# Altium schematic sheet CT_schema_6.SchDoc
size 287 x 160 mm
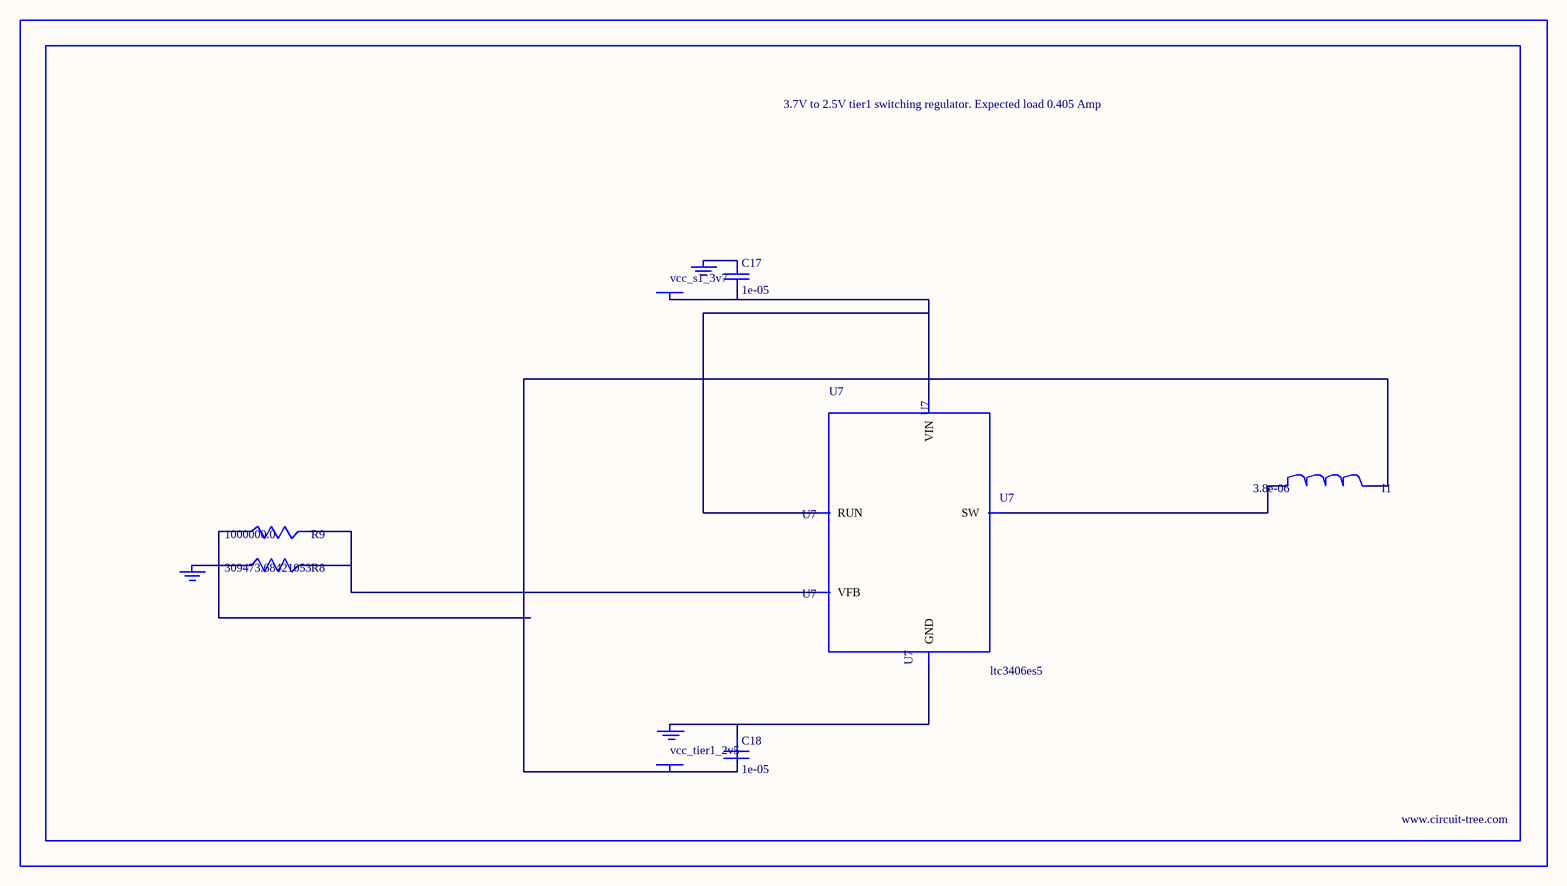
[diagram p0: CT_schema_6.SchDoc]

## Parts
BORDER5  (no value)
C17  1e-05  [C0805]
C18  1e-05  [C0805]
GND_INSTANCE_5_0  (no value)
GND_INSTANCE_5_1  (no value)
GND_INSTANCE_5_2  (no value)
I1  3.8e-06  [DR1040]
POWER_INSTANCE_5_0  vcc_tier1_2v5
POWER_INSTANCE_5_1  vcc_s1_3v7
R8  309473.68421053  [R0603]
R9  1000000.0  [R0603]
U7  ltc3406es5  [TSOT-23-5]

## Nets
NetC17_1: C17.1 GND_INSTANCE_5_1.0(GND)
NetC17_2: C17.2 POWER_INSTANCE_5_1.0(PWR) U7.1(RUN) U7.4(VIN)
NetC18_1: C18.1 GND_INSTANCE_5_0.0(GND) U7.2(GND)
NetC18_2: C18.2 I1.2 POWER_INSTANCE_5_0.0(PWR) R9.1
NetGND_INSTANCE_5_2_0: GND_INSTANCE_5_2.0(GND) R8.1
NetI1_1: I1.1 U7.3(SW)
NetR8_2: R8.2 R9.2 U7.5(VFB)

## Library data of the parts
BORDER5 = BORDER_PAGE5
C17 C18 = C0805C106K8RACTU
GND_INSTANCE_5_0-GND_INSTANCE_5_2 = GND
I1 = DR1040-3R8-R
POWER_INSTANCE_5_0 POWER_INSTANCE_5_1 = PWR
R8 = R8
R9 = RC0603JR-071ML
